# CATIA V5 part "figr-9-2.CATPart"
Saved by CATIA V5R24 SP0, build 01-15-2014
Part number: Part1
Bounding box of the stored display mesh (mm): x -25 to 69.61, y -139.735 to 0, z 0 to 45
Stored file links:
  D:\KAVITA\CATIA V5-6R2014 Project_ Kavita\CATIA V5-6R2014_partfiles\Partfiles\c09_catia_v5-6r2014_prt\figr-9-2.CATPart
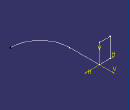
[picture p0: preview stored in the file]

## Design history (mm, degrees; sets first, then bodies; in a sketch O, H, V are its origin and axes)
Body1 (main body)
  Sketch1 on xy-plane, origin (0, 0, 0), H (1, 0, 0), V (0, 1, 0)
    line L1 (0, 0) -> (0, -70.1255)
    arc A1 centre (69.6095, -70.1255) radius 69.6095 from (0, -70.1255) to (69.6095, -139.7351) ccw
    vertical: L1 V
    tangency: A1 L1
  Sketch2 on zx-plane, origin (0, 0, 0), H (-1, 0, 0), V (0, 0, 1)
    point P1 (0, 0)
    line L1 (0, 0) -> (25, 0)
    line L2 (25, 0) -> (25, 45)
    line L3 (25, 45) -> (0, 45)
    line L4 (0, 45) -> (0, 0)
    length L3 = 25
    length L2 = 45
    coincidence: P1 H, P1 O
    horizontal: L1 H, L3 H
    vertical: L2 V, L4 V
  Rib1: profile Sketch2, centre curve Sketch1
